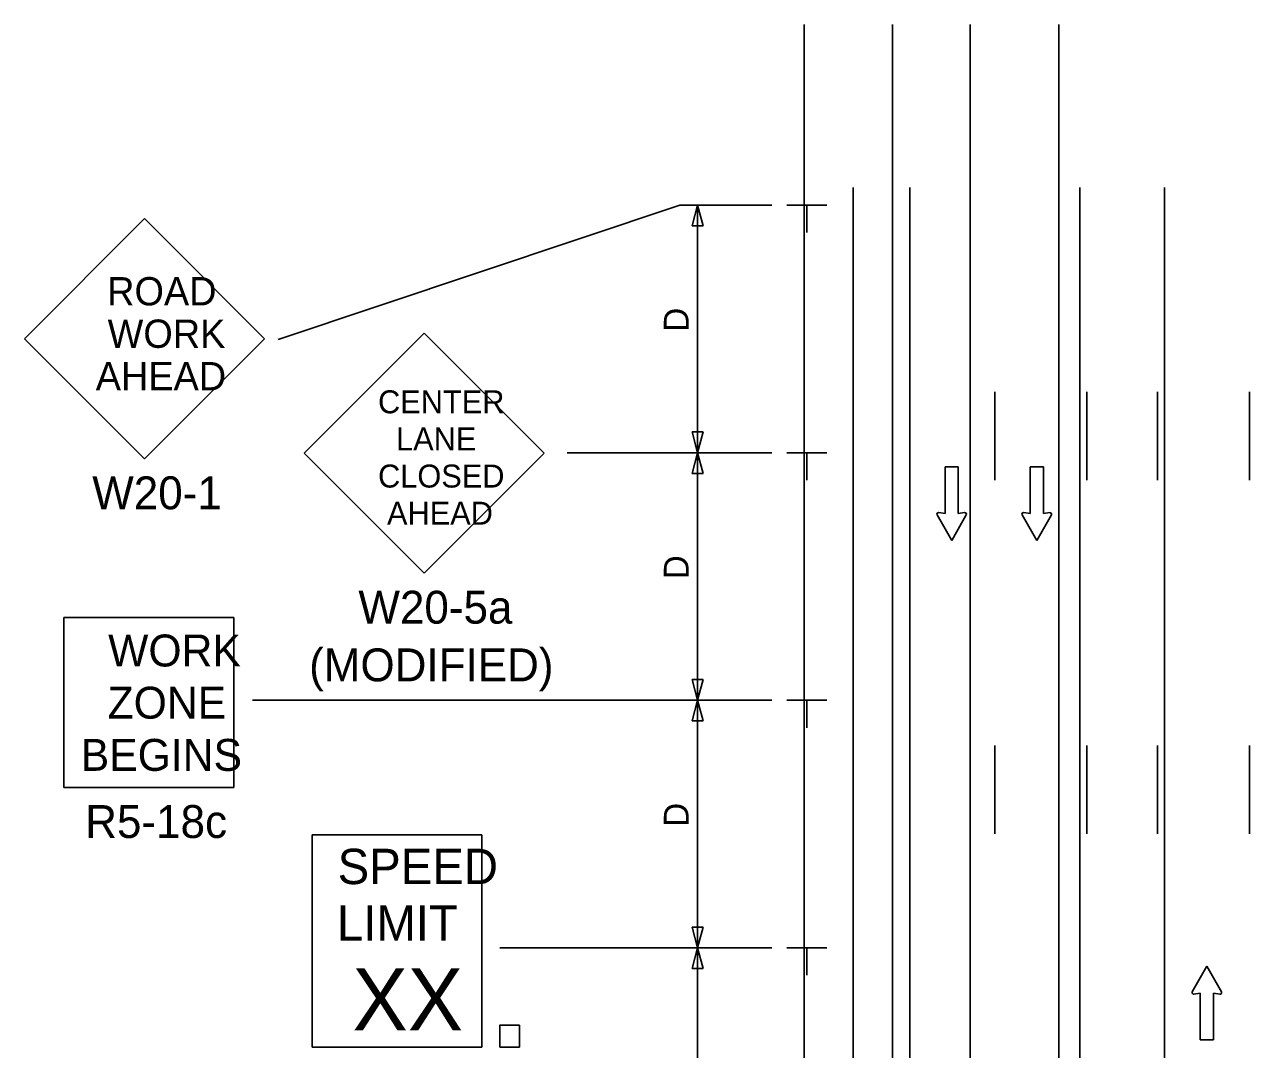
# Model space of a CAD drawing. Extents: x 16743 to 18475, y 7218 to 8262.
# Drawn here: x 16742.8 to 17089.1, y 7972.5 to 8262.3 of the extents above; entities that cross this region are included whole.
import ezdxf

# ---------------------------------------------------------------- set-up
doc = ezdxf.new("R2010")
doc.units = 0
for name, color, linetype in [('ALI_LEGAL_EX', 7, 'Continuous'), ('MT_SCRATCH_LEVEL_E', 7, 'Continuous'), ('PAVT_EDGE_EX', 7, 'Continuous'), ('TRAFFIC_SIGNS_PR', 7, 'Continuous'), ('TYPICAL_TEXT_DIMEN_PR', 7, 'Continuous')]:
    doc.layers.add(name, color=color, linetype=linetype)

msp = doc.modelspace()

# ---------------------------------------------------------------- linework, layer by layer
at = {"layer": 'ALI_LEGAL_EX'}
for points in [[(17017.08, 8158.47), (17017.08, 8133.47)], [(17043.08, 8158.47), (17043.08, 8133.47)], [(17063.08, 8158.47), (17063.08, 8133.47)], [(17089.08, 8158.47), (17089.08, 8133.47)], [(17017.08, 8058.47), (17017.08, 8033.47)], [(17043.08, 8058.47), (17043.08, 8033.47)], [(17063.08, 8058.47), (17063.08, 8033.47)], [(17089.08, 8058.47), (17089.08, 8033.47)]]:
    msp.add_lwpolyline(points, dxfattribs=at)
at = {"layer": 'MT_SCRATCH_LEVEL_E'}
for p, q in [((17006.75, 8137.27), (17003.01, 8137.27)), ((17003.01, 8137.27), (17003.01, 8124.01)), ((17006.75, 8137.27), (17003.01, 8137.27)), ((17003.01, 8137.27), (17003.01, 8124.01)), ((17006.75, 8124.01), (17006.75, 8137.27)), ((17006.75, 8124.01), (17006.75, 8137.27)), ((17030.82, 8137.27), (17027.08, 8137.27)), ((17027.08, 8137.27), (17027.08, 8124.01)), ((17030.82, 8137.27), (17027.08, 8137.27)), ((17027.08, 8137.27), (17027.08, 8124.01)), ((17030.82, 8124.01), (17030.82, 8137.27)), ((17030.82, 8124.01), (17030.82, 8137.27)), ((17003.01, 8124.01), (17001.23, 8124.32)), ((17003.01, 8124.01), (17001.23, 8124.32)), ((17008.53, 8124.32), (17006.75, 8124.01)), ((17008.53, 8124.32), (17006.75, 8124.01)), ((17027.08, 8124.01), (17025.3, 8124.32)), ((17027.08, 8124.01), (17025.3, 8124.32)), ((17032.6, 8124.32), (17030.82, 8124.01)), ((17032.6, 8124.32), (17030.82, 8124.01)), ((17000.75, 8123.64), (17004.9, 8116.4)), ((17000.75, 8123.64), (17004.9, 8116.4)), ((17004.9, 8116.4), (17009.01, 8123.64)), ((17004.9, 8116.4), (17009.01, 8123.64)), ((17024.82, 8123.64), (17028.97, 8116.4)), ((17024.82, 8123.64), (17028.97, 8116.4)), ((17028.97, 8116.4), (17033.08, 8123.64)), ((17028.97, 8116.4), (17033.08, 8123.64)), ((17077.02, 7996.03), (17072.9, 7988.79)), ((17077.02, 7996.03), (17072.9, 7988.79)), ((17081.16, 7988.79), (17077.02, 7996.03)), ((17081.16, 7988.79), (17077.02, 7996.03)), ((17073.39, 7988.11), (17075.16, 7988.43)), ((17073.39, 7988.11), (17075.16, 7988.43)), ((17075.16, 7988.43), (17075.16, 7975.17)), ((17075.16, 7988.43), (17075.16, 7975.17)), ((17078.91, 7975.17), (17078.91, 7988.43)), ((17078.91, 7988.43), (17080.68, 7988.11)), ((17078.91, 7975.17), (17078.91, 7988.43)), ((17078.91, 7988.43), (17080.68, 7988.11)), ((17075.16, 7975.17), (17078.91, 7975.17)), ((17075.16, 7975.17), (17078.91, 7975.17))]:
    msp.add_line(p, q, dxfattribs=at)
for centre, start, end in [((17001.16, 8123.86), 80.0362, 209.7731), ((17001.16, 8123.86), 80.0362, 209.7731), ((17008.6, 8123.86), 330.4248, 99.9638), ((17008.6, 8123.86), 330.4248, 99.9638), ((17025.23, 8123.86), 80.0362, 209.7731), ((17025.23, 8123.86), 80.0362, 209.7731), ((17032.67, 8123.86), 330.4248, 99.9638), ((17032.67, 8123.86), 330.4248, 99.9638), ((17073.31, 7988.57), 150.4248, 279.9638), ((17073.31, 7988.57), 150.4248, 279.9638), ((17080.75, 7988.57), 260.0362, 29.7731), ((17080.75, 7988.57), 260.0362, 29.7731)]:
    msp.add_arc(centre, 0.463, start, end, dxfattribs=at)
at = {"layer": 'PAVT_EDGE_EX'}
for p, q in [((16963.15, 8262.34), (16963.15, 7433.15)), ((16988.15, 8262.34), (16988.15, 7433.15)), ((17010.15, 8262.34), (17010.15, 7433.15)), ((17035.15, 8262.34), (17035.15, 7433.15)), ((16977.08, 8216.25), (16977.08, 7378.68)), ((16993.08, 8216.25), (16993.08, 7378.68)), ((17041.08, 8216.25), (17041.08, 7378.68)), ((17065.08, 8216.25), (17065.08, 7378.68))]:
    msp.add_line(p, q, dxfattribs=at)
at = {"layer": 'TRAFFIC_SIGNS_PR'}
for p, q in [((16776.74, 8207.43), (16742.8, 8173.49)), ((16810.68, 8173.49), (16776.74, 8207.43)), ((16742.8, 8173.49), (16776.74, 8139.55)), ((16776.74, 8139.55), (16810.68, 8173.49)), ((16855.77, 8175.08), (16821.82, 8141.14)), ((16889.71, 8141.14), (16855.77, 8175.08)), ((16821.82, 8141.14), (16855.77, 8107.2)), ((16855.77, 8107.2), (16889.71, 8141.14)), ((16753.94, 8046.6), (16753.94, 8094.6)), ((16753.94, 8094.6), (16801.94, 8094.6)), ((16801.94, 8046.6), (16801.94, 8094.6)), ((16753.94, 8046.6), (16801.94, 8046.6)), ((16824.11, 8033.18), (16872.11, 8033.18)), ((16824.11, 7973.18), (16824.11, 8033.18)), ((16872.11, 7973.18), (16872.11, 8033.18)), ((16824.11, 7973.18), (16872.11, 7973.18))]:
    msp.add_line(p, q, dxfattribs=at)
msp.add_lwpolyline([(16877.13, 7973.18), (16882.72, 7973.18), (16882.72, 7979.35), (16877.13, 7979.35)], close=True, dxfattribs=at)
at = {"layer": 'TYPICAL_TEXT_DIMEN_PR'}
for p, q in [((16928.08, 8211.25), (16814.46, 8173.27)), ((16928.08, 8211.25), (16954.08, 8211.25)), ((16931.51, 8205.39), (16933.08, 8211.25)), ((16933.08, 8141.25), (16933.08, 8211.25)), ((16933.08, 8211.25), (16934.65, 8205.39)), ((16958.33, 8211.25), (16969.58, 8211.25)), ((16963.96, 8211.25), (16963.96, 8203.47)), ((16933.08, 8205.39), (16931.51, 8205.39)), ((16934.65, 8205.39), (16933.08, 8205.39)), ((16933.08, 8141.25), (16931.51, 8147.11)), ((16931.51, 8147.11), (16933.08, 8147.11)), ((16933.08, 8147.11), (16934.65, 8147.11)), ((16934.65, 8147.11), (16933.08, 8141.25)), ((16896.22, 8141.25), (16954.08, 8141.25)), ((16931.51, 8135.39), (16933.08, 8141.25)), ((16933.08, 8141.25), (16934.65, 8135.39)), ((16933.08, 8071.25), (16933.08, 8141.25)), ((16958.33, 8141.25), (16969.58, 8141.25)), ((16963.96, 8141.25), (16963.96, 8133.47)), ((16933.08, 8135.39), (16931.51, 8135.39)), ((16934.65, 8135.39), (16933.08, 8135.39)), ((16933.08, 8071.25), (16931.51, 8077.11)), ((16931.51, 8077.11), (16933.08, 8077.11)), ((16933.08, 8077.11), (16934.65, 8077.11)), ((16934.65, 8077.11), (16933.08, 8071.25)), ((16807.27, 8071.25), (16954.08, 8071.25)), ((16931.51, 8065.39), (16933.08, 8071.25)), ((16933.08, 8001.25), (16933.08, 8071.25)), ((16933.08, 8071.25), (16934.65, 8065.39)), ((16958.33, 8071.25), (16969.58, 8071.25)), ((16963.96, 8071.25), (16963.96, 8063.47)), ((16933.08, 8065.39), (16931.51, 8065.39)), ((16934.65, 8065.39), (16933.08, 8065.39)), ((16933.08, 8001.25), (16931.51, 8007.11)), ((16931.51, 8007.11), (16933.08, 8007.11)), ((16933.08, 8007.11), (16934.65, 8007.11)), ((16934.65, 8007.11), (16933.08, 8001.25)), ((16877.19, 8001.25), (16954.08, 8001.25)), ((16931.51, 7995.39), (16933.08, 8001.25)), ((16933.08, 7931.25), (16933.08, 8001.25)), ((16933.08, 8001.25), (16934.65, 7995.39)), ((16958.33, 8001.25), (16969.58, 8001.25)), ((16963.96, 8001.25), (16963.96, 7993.47)), ((16933.08, 7995.39), (16931.51, 7995.39)), ((16934.65, 7995.39), (16933.08, 7995.39)), ((16933.08, 7976.38), (16933.08, 7980.15))]:
    msp.add_line(p, q, dxfattribs=at)

# ---------------------------------------------------------------- texts
at = {"layer": 'TRAFFIC_SIGNS_PR'}
for s, height, p in [('ROAD', 8, (16766.17, 8182.9)), ('WORK', 8, (16766.3, 8170.9)), ('AHEAD', 8, (16762.94, 8158.9)), ('W20-1', 9.3, (16761.95, 8125.25)), ('W20-5a', 9.3, (16837.19, 8092.9)), ('WORK', 9.021, (16766.44, 8080.8)), ('(MODIFIED)', 9.3, (16823.26, 8076.6)), ('ZONE', 9.021, (16766.29, 8066.04)), ('BEGINS', 9.021, (16758.7, 8051.28)), ('R5-18c', 9.3, (16759.96, 8032.3)), ('SPEED', 10, (16831.32, 8019.25)), ('LIMIT', 10, (16831.12, 8003.25)), ('XX', 17.538, (16835.5, 7977.87))]:
    msp.add_text(s, height=height, dxfattribs=at).set_placement(p)
at = {"layer": 'TYPICAL_TEXT_DIMEN_PR'}
for p in [(16930.52, 8175.47), (16930.52, 8105.47), (16930.52, 8035.47)]:
    msp.add_text('D', height=7, rotation=90, dxfattribs=at).set_placement(p)
for s, p in [('CENTER', (16842.74, 8152.39)), ('LANE', (16847.83, 8141.89)), ('CLOSED', (16842.74, 8131.39)), ('AHEAD', (16845.27, 8120.89))]:
    msp.add_text(s, height=6.5, dxfattribs=at).set_placement(p)

doc.saveas('drawing.dxf')
